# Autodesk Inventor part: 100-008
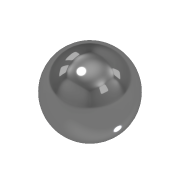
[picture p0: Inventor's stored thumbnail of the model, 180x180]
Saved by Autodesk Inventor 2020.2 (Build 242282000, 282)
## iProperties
Created: 2014-01
Part Number: 100-008
Material: Ogólny
Document SubType Name: Modeling
Designer: F.Stasiak
Density: 1 g/cm^3
Appearance: Chrom - czarny polerowany
Manager: www.cadconsulting.pl
Company: Fabian Stasiak CAD Consulting
Author: F.Stasiak
Subject: Zbiór ćwiczeń. Autodesk Inventor 2020. Kurs podstawowy
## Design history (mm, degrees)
sketch "Szkic1"
  geometry: L1 (0, 0)-(0, 57.272); L2 (-12.5, 0)-(0, 0); A1 r 30 centre (0, 27.272) between (0, 57.272) and (-12.5, 0)
  constraints: 4 end point, 2 point on circle, 1 centre point, 1 perpendicular, 1 point on line, 1 vertical
  dimensions: "d0" = 25 diameter of L2.start L1; "d1" = 30 radius of A1
revolve "Obrót1" sketch "Szkic1" stored, may be unused: angle "d2" = 90 deg
hole "Otwór1" diameter "d5" = 6.647; stored, may be unused: countersink angle "d9" = 90 deg, drill point angle "d11" = 118 deg; dims "d3" = 10, "d4" = 10, "d6" = 6, "d7" = 4, "d8" = 2, "d10" = 25
node "Bryła1"
